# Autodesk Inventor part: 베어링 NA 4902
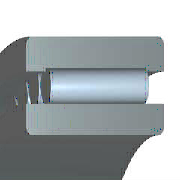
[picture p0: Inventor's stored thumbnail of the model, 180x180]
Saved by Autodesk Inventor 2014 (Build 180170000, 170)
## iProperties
IsCustomPart: 1
Created: 2012-02
Part Number: 베어링 NA 4902
Material: 강철, 연강
Description: 니들 롤러 베어링 - 경계 치수 및 공차
Document SubType Name: Modeling
Standard: KS B 2029
Designer: mduedu
Standards Organization: KS
Language: ko-KR
Size Designation: NA 4902 - 15 x 28 x 13
Categories: <MemberInstance><Categories><Category DisplayName="샤프트 부품" InternalName="7f7aeb1f-a693-4053-b835-cee3144e0d98" Mnemonic="SHFT"><Category DisplayName="베어링" Inter
Density: 7.86 g/cm^3
Appearance: 노란색
Mass: 37.7482 g
Surface Area: 52.7153 cm^2
Volume: 4.80256 cm^3
Author: mduedu
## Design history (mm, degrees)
sketch "스케치"
  geometry: L1 (1.857, 11.5)-(11.143, 11.5); L2 (11.143, 11.5)-(11.143, 10); L3 (13, 10)-(0, 10); L4 (1.857, 10)-(1.857, 11.5); L5 (1.857, 10.75)-(11.143, 10.75); L6 (6.5, 10.75)-(6.5, 10); L7 (0, 7.5)-(13, 7.5); L8 (0, 14)-(13, 14); L9 (13, 7.5)-(13, 10); L10 (13, 11.35)-(13, 14); L11 (1.857, 11.35)-(0, 11.35); L12 (11.143, 11.35)-(13, 11.35); L13 (-6, 0)-(36, 0) reference; L14 (0, -1.9)-(0, 14.9) reference
  constraints: 24 end point, 8 point on line, 3 midpoint, 3 parallel, 3 perpendicular, 2 symmetric about line, 1 horizontal, 1 other
  dimensions: "d6" = 15 diameter of L7 L13 (= WD); "d7" = 20 diameter of L3 L13 (= KID1); "d8" = 28 diameter of L8 L13 (= BD); "d9" = 21.5 diameter of L6.start L13 (= 0.5 x WD + 0.5 x BD); "d10" = 22.7 diameter of L12 L13 (= 0.9 x BD + 0.9 x WD - 0.8 x KID1); "d11" = 23 diameter of L1 L13 (= BD + WD - KID1); "d12" = 1.85714 distance between parallel lines of L14 L4 (= 0.142857 x KB); "d13" = 13 distance between parallel lines of L14 L9 (= KB); "d14" = 11.14286 distance between parallel lines of L14 L2 (= 0.857143 x KB)
revolve "본체" stored, may be unused: angle "d17" = 90 deg
revolve "롤러" stored, may be unused: angle "d18" = 90 deg
node "작업 평면1"
body "Solid1"
fillet "모깎기1" dims "d0" = 0.3 (= KRS)
pattern_circular "IDS_ARRAYROLLER[SIMPL:T]" dims angle "d2" = 360 deg
other parameters: "WD" = 15 [user parameter; used in 6 equation terms], "BD" = 28 [user parameter; used in 6 equation terms], "KB" = 13 [user parameter; used in 3 equation terms], "KID1" = 20 [user parameter; used in 4 equation terms], "KRS" = 0.3 [user parameter; used in 1 equation term], "d3" = 0, "d4" = 0, "d5" = 0, "d15" = 0, "d16" = 0, "BC0" = 1.37e+07 [user parameter], "WR" = 7.5 (= 0.5 x WD) [user parameter], "BBA" = 0 [user parameter], "BC" = 1.02e+07 [user parameter], "BR" = 14 (= 0.5 x BD) [user parameter]
